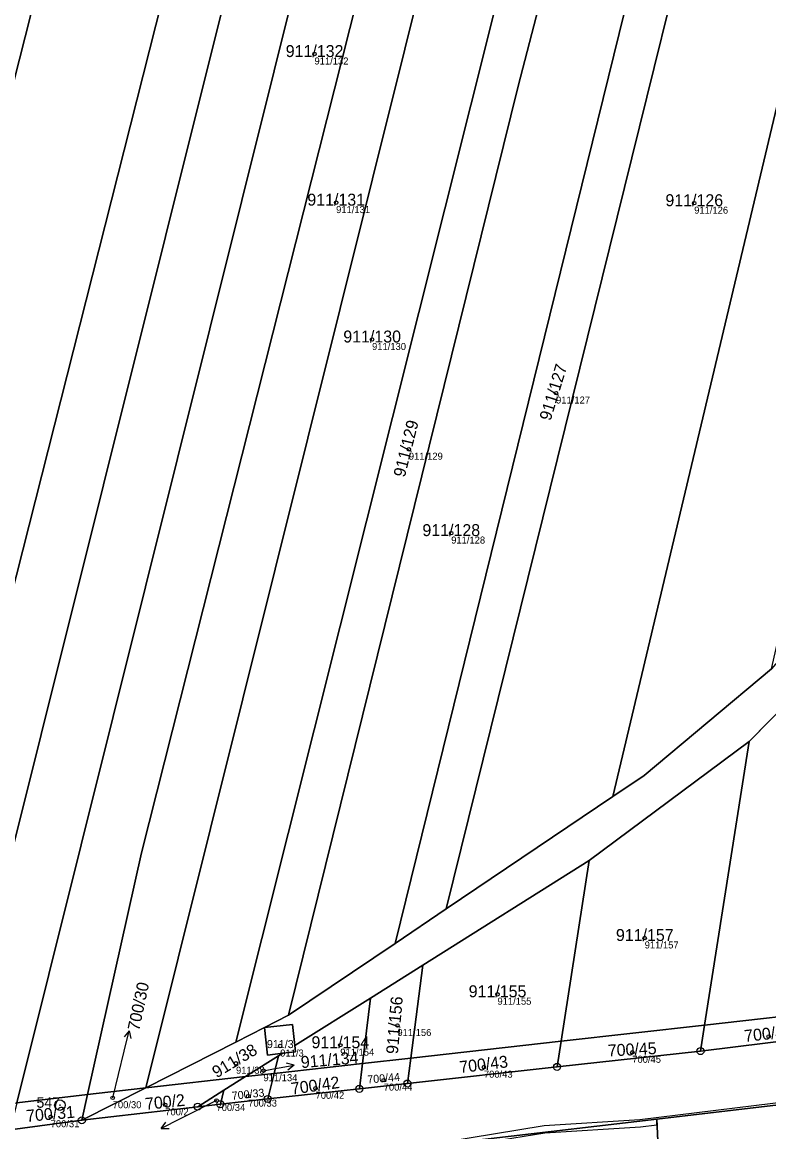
# Model space of a CAD drawing. Extents: x -603967 to -594699, y -1179315 to -1165625.
# Drawn here: x -596821.9 to -596715.6, y -1172077.4 to -1171919.4 of the extents above; entities that cross this region are included whole.
import ezdxf

# ---------------------------------------------------------------- set-up
doc = ezdxf.new("R2010")
doc.units = 0
for name, color, linetype in [('Definiční body', 7, 'Continuous'), ('Hranice parcel', 7, 'Continuous'), ('Parcelní čísla', 7, 'Continuous'), ('Polygon parcely', 7, 'Continuous'), ('Pop  PČ popisy', 7, 'Continuous'), ('Věcná břemena k části', 7, 'Continuous'), ('Značky bodu BP', 7, 'Continuous')]:
    doc.layers.add(name, color=color, linetype=linetype)

msp = doc.modelspace()

# ---------------------------------------------------------------- linework, layer by layer
at = {"layer": 'Definiční body'}
for centre in [(-596780.26, -1171923.92994), (-596777.18, -1171945.08994), (-596726.18, -1171945.16994), (-596772.06, -1171964.57994), (-596745.85, -1171972.20994), (-596766.82, -1171980.20994), (-596760.79, -1171992.14994), (-596733.23, -1172049.80994), (-596754.2, -1172057.81994), (-596768.45, -1172062.26994), (-596715.56, -1172063.82994), (-596785.14, -1172065.19994), (-596776.59, -1172065.07994), (-596735, -1172066.08994), (-596791.44, -1172067.64994), (-596787.53, -1172068.70994), (-596756.13, -1172068.20994), (-596770.4, -1172070.04994), (-596780.11, -1172071.21994), (-596809, -1172072.55994), (-596794.22, -1172072.94994), (-596789.7, -1172072.32994), (-596801.52, -1172073.56994), (-596817.84, -1172075.26994)]:
    msp.add_circle(centre, 0.25, dxfattribs=at)
at = {"layer": 'Hranice parcel'}
for p, q in [((-596718.34, -1172021.81), (-596692.4, -1171995.43)), ((-596741.13, -1172038.79), (-596718.34, -1172021.81)), ((-596724.7, -1172062.23), (-596718.34, -1172021.81)), ((-596737.77, -1172029.67), (-596761.52, -1172045.67)), ((-596764.85, -1172053.69), (-596741.13, -1172038.79)), ((-596745.13, -1172064.52), (-596741.13, -1172038.79)), ((-596761.52, -1172045.67), (-596768.78, -1172050.57)), ((-596768.78, -1172050.57), (-596783.97, -1172060.8)), ((-596772.3, -1172058.37), (-596764.85, -1172053.69)), ((-596764.85, -1172053.69), (-596766.56, -1172066.92)), ((-596783.08, -1172065.14), (-596772.3, -1172058.37)), ((-596773.43, -1172067.69), (-596772.3, -1172058.37)), ((-596705.38, -1172060.06), (-596724.7, -1172062.23)), ((-596783.97, -1172060.8), (-596787.39, -1172062.57)), ((-596787.39, -1172062.57), (-596783.41, -1172062.12)), ((-596783.41, -1172062.12), (-596783.08, -1172065.14)), ((-596787.39, -1172062.57), (-596791.46, -1172064.64)), ((-596786.95, -1172066.47), (-596787.39, -1172062.57)), ((-596724.7, -1172062.23), (-596745.13, -1172064.52)), ((-596725.28, -1172065.92), (-596724.7, -1172062.23)), ((-596725.28, -1172065.92), (-596706.08, -1172063.55)), ((-596791.46, -1172064.64), (-596804.29, -1172071.14)), ((-596745.13, -1172064.52), (-596766.56, -1172066.92)), ((-596745.71, -1172068.16), (-596745.13, -1172064.52)), ((-596790.08, -1172069.55), (-596785.41, -1172066.61)), ((-596784.79, -1172066.22), (-596786.95, -1172066.47)), ((-596786.02, -1172069.1), (-596785.41, -1172066.61)), ((-596785.41, -1172066.61), (-596784.79, -1172066.22)), ((-596766.56, -1172066.92), (-596773.43, -1172067.69)), ((-596766.56, -1172066.92), (-596767.02, -1172070.53)), ((-596745.71, -1172068.16), (-596725.28, -1172065.92)), ((-596773.43, -1172067.69), (-596786.02, -1172069.1)), ((-596773.87, -1172071.29), (-596773.43, -1172067.69)), ((-596767.02, -1172070.53), (-596745.71, -1172068.16)), ((-596790.08, -1172069.55), (-596804.29, -1172071.14)), ((-596793.18, -1172071.5), (-596790.08, -1172069.55)), ((-596786.02, -1172069.1), (-596790.08, -1172069.55)), ((-596786.92, -1172072.73), (-596786.02, -1172069.1)), ((-596804.29, -1172071.14), (-596813.4, -1172075.77)), ((-596796.88, -1172073.83), (-596793.18, -1172071.5)), ((-596793.18, -1172071.5), (-596793.67, -1172073.48)), ((-596786.92, -1172072.73), (-596773.87, -1172071.29)), ((-596773.87, -1172071.29), (-596767.02, -1172070.53)), ((-596812.58, -1172072.1), (-596822.64, -1172073.28)), ((-596812.58, -1172072.1), (-596813.4, -1172075.77)), ((-596793.67, -1172073.48), (-596786.92, -1172072.73)), ((-596709.32, -1172073.01), (-596731.52, -1172075.61)), ((-596813.4, -1172075.77), (-596796.88, -1172073.83)), ((-596796.88, -1172073.83), (-596793.67, -1172073.48)), ((-596823.6, -1172077.13), (-596813.4, -1172075.77)), ((-596731.52, -1172075.61), (-596755.09, -1172078.34)), ((-596731.52, -1172075.61), (-596729.67, -1172116))]:
    msp.add_line(p, q, dxfattribs=at)
for points in [[(-596860.64, -1172079.9), (-596855.65, -1172056.04), (-596784.82, -1171776.95), (-596751.75, -1171640.6)], [(-596842.58, -1172076.46), (-596782.13, -1171837.9), (-596745.57, -1171692.32), (-596733.85, -1171640.88)], [(-596725.01, -1171641.01), (-596749.75, -1171743.78), (-596774.96, -1171843.56), (-596828.06, -1172056.21), (-596832.9, -1172074.65)], [(-596715.61, -1171641.15), (-596731.07, -1171706.01), (-596822.64, -1172073.28)], [(-596706.66, -1171641.29), (-596723.53, -1171715.68), (-596804.88, -1172037.67), (-596812.58, -1172072.1)], [(-596698.11, -1171641.43), (-596716.69, -1171719.87), (-596804.29, -1172071.14)], [(-596688.26, -1171641.58), (-596691.61, -1171658.85), (-596709.62, -1171738.29), (-596791.46, -1172064.64)], [(-596680.83, -1171641.69), (-596726.19, -1171831.91), (-596751.27, -1171928.52), (-596783.97, -1172060.8)], [(-596671.46, -1171641.83), (-596677.57, -1171672.4), (-596701.96, -1171779.19), (-596768.78, -1172050.57)], [(-596666.17, -1171641.91), (-596670.71, -1171668.9), (-596684.25, -1171728.86), (-596700.1, -1171797.33), (-596761.52, -1172045.67)], [(-596651.64, -1171642.14), (-596655.01, -1171667.88), (-596688.58, -1171822.7), (-596737.77, -1172029.67)], [(-596715.18, -1172011.49), (-596733.29, -1172026.65), (-596737.77, -1172029.67)], [(-596783.08, -1172065.14), (-596782.98, -1172066.02), (-596784.79, -1172066.22)], [(-596804.29, -1172071.14), (-596806.36, -1172071.37), (-596812.58, -1172072.1)]]:
    msp.add_lwpolyline(points, dxfattribs=at)
at = {"layer": 'Polygon parcely'}
for points in [[(-596784.82, -1171776.95), (-596751.75, -1171640.6), (-596757.97, -1171640.5), (-596768.62, -1171640.34), (-596798.16, -1171764.25), (-596861.99, -1172011.73), (-596875.03, -1172065.74), (-596878.39, -1172083.56), (-596860.64, -1172079.9), (-596855.65, -1172056.04)], [(-596782.13, -1171837.9), (-596745.57, -1171692.32), (-596733.85, -1171640.88), (-596743.82, -1171640.72), (-596751.75, -1171640.6), (-596784.82, -1171776.95), (-596855.65, -1172056.04), (-596860.64, -1172079.9), (-596856.7, -1172079.09), (-596842.58, -1172076.46)], [(-596842.58, -1172076.46), (-596832.9, -1172074.65), (-596828.06, -1172056.21), (-596774.96, -1171843.56), (-596749.75, -1171743.78), (-596725.01, -1171641.01), (-596732.91, -1171640.89), (-596733.85, -1171640.88), (-596745.57, -1171692.32), (-596782.13, -1171837.9)], [(-596828.06, -1172056.21), (-596832.9, -1172074.65), (-596830.41, -1172074.19), (-596822.64, -1172073.28), (-596731.07, -1171706.01), (-596715.61, -1171641.15), (-596720.4, -1171641.08), (-596725.01, -1171641.01), (-596749.75, -1171743.78), (-596774.96, -1171843.56)], [(-596822.64, -1172073.28), (-596812.58, -1172072.1), (-596804.88, -1172037.67), (-596723.53, -1171715.68), (-596706.66, -1171641.29), (-596715.61, -1171641.15), (-596731.07, -1171706.01)], [(-596812.58, -1172072.1), (-596806.36, -1172071.37), (-596804.29, -1172071.14), (-596716.69, -1171719.87), (-596698.11, -1171641.43), (-596705.63, -1171641.31), (-596706.66, -1171641.29), (-596723.53, -1171715.68), (-596804.88, -1172037.67)], [(-596804.29, -1172071.14), (-596791.46, -1172064.64), (-596709.62, -1171738.29), (-596691.61, -1171658.85), (-596688.26, -1171641.58), (-596693.33, -1171641.5), (-596698.11, -1171641.43), (-596716.69, -1171719.87)], [(-596709.62, -1171738.29), (-596791.46, -1172064.64), (-596787.39, -1172062.57), (-596783.97, -1172060.8), (-596751.27, -1171928.52), (-596726.19, -1171831.91), (-596680.83, -1171641.69), (-596688.26, -1171641.58), (-596691.61, -1171658.85)], [(-596783.97, -1172060.8), (-596768.78, -1172050.57), (-596701.96, -1171779.19), (-596677.57, -1171672.4), (-596671.46, -1171641.83), (-596680.83, -1171641.69), (-596726.19, -1171831.91), (-596751.27, -1171928.52)], [(-596768.78, -1172050.57), (-596761.52, -1172045.67), (-596700.1, -1171797.33), (-596684.25, -1171728.86), (-596670.71, -1171668.9), (-596666.17, -1171641.91), (-596667.7, -1171641.89), (-596671.46, -1171641.83), (-596677.57, -1171672.4), (-596701.96, -1171779.19)], [(-596670.71, -1171668.9), (-596684.25, -1171728.86), (-596700.1, -1171797.33), (-596761.52, -1172045.67), (-596737.77, -1172029.67), (-596688.58, -1171822.7), (-596655.01, -1171667.88), (-596651.64, -1171642.14), (-596655.52, -1171642.08), (-596666.17, -1171641.91)], [(-596655.01, -1171667.88), (-596688.58, -1171822.7), (-596737.77, -1172029.67), (-596733.29, -1172026.65), (-596715.18, -1172011.49), (-596666.38, -1171798.6), (-596652.52, -1171725.52), (-596641, -1171673.92), (-596638.2, -1171642.35), (-596642.55, -1171642.28), (-596651.64, -1171642.14)], [(-596705.38, -1172060.06), (-596692.4, -1171995.43), (-596718.34, -1172021.81), (-596724.7, -1172062.23)], [(-596724.7, -1172062.23), (-596718.34, -1172021.81), (-596741.13, -1172038.79), (-596745.13, -1172064.52)], [(-596766.56, -1172066.92), (-596745.13, -1172064.52), (-596741.13, -1172038.79), (-596764.85, -1172053.69)], [(-596773.43, -1172067.69), (-596766.56, -1172066.92), (-596764.85, -1172053.69), (-596772.3, -1172058.37)], [(-596782.98, -1172066.02), (-596784.79, -1172066.22), (-596785.41, -1172066.61), (-596786.02, -1172069.1), (-596773.43, -1172067.69), (-596772.3, -1172058.37), (-596783.08, -1172065.14)], [(-596725.28, -1172065.92), (-596706.08, -1172063.55), (-596705.38, -1172060.06), (-596724.7, -1172062.23)], [(-596786.95, -1172066.47), (-596784.79, -1172066.22), (-596782.98, -1172066.02), (-596783.08, -1172065.14), (-596783.41, -1172062.12), (-596787.39, -1172062.57)], [(-596787.39, -1172062.57), (-596791.46, -1172064.64), (-596804.29, -1172071.14), (-596790.08, -1172069.55), (-596785.41, -1172066.61), (-596784.79, -1172066.22), (-596786.95, -1172066.47)], [(-596725.28, -1172065.92), (-596724.7, -1172062.23), (-596745.13, -1172064.52), (-596745.71, -1172068.16)], [(-596767.02, -1172070.53), (-596745.71, -1172068.16), (-596745.13, -1172064.52), (-596766.56, -1172066.92)], [(-596786.02, -1172069.1), (-596785.41, -1172066.61), (-596790.08, -1172069.55)], [(-596773.87, -1172071.29), (-596767.02, -1172070.53), (-596766.56, -1172066.92), (-596773.43, -1172067.69)], [(-596786.92, -1172072.73), (-596773.87, -1172071.29), (-596773.43, -1172067.69), (-596786.02, -1172069.1)], [(-596813.4, -1172075.77), (-596796.88, -1172073.83), (-596793.18, -1172071.5), (-596790.08, -1172069.55), (-596804.29, -1172071.14)], [(-596786.92, -1172072.73), (-596786.02, -1172069.1), (-596790.08, -1172069.55), (-596793.18, -1172071.5), (-596793.67, -1172073.48)], [(-596813.4, -1172075.77), (-596804.29, -1172071.14), (-596806.36, -1172071.37), (-596812.58, -1172072.1)], [(-596793.67, -1172073.48), (-596793.18, -1172071.5), (-596796.88, -1172073.83)], [(-596813.4, -1172075.77), (-596812.58, -1172072.1), (-596822.64, -1172073.28), (-596823.6, -1172077.13)], [(-596729.67, -1172116), (-596707.12, -1172113.29), (-596709.32, -1172073.01), (-596731.52, -1172075.61)], [(-596755.09, -1172078.34), (-596754.53, -1172125.79), (-596739.79, -1172124.76), (-596740.18, -1172117.22), (-596729.67, -1172116), (-596731.52, -1172075.61)]]:
    msp.add_lwpolyline(points, close=True, dxfattribs=at)
for points in [[(-596783.08, -1172065.14), (-596772.3, -1172058.37), (-596764.85, -1172053.69), (-596741.13, -1172038.79), (-596718.34, -1172021.81), (-596692.4, -1171995.43), (-596668.6, -1171971.23), (-596660.59, -1171963.08), (-596653.35, -1171955.72), (-596646.21, -1171948.46), (-596637.9, -1171939.47), (-596630.53, -1171929.86), (-596623.06, -1171920.13), (-596616.01, -1171912.53), (-596609.77, -1171907.25), (-596600.89, -1171899.73), (-596594.45, -1171894.83), (-596587.53, -1171889.33), (-596580.8, -1171885.78), (-596574.08, -1171882.1), (-596567.57, -1171878.54), (-596560.55, -1171874.7), (-596553.65, -1171870.92)], [(-596627.33, -1171917.09), (-596634.75, -1171928.19), (-596644.04, -1171942.08), (-596651.33, -1171948.59), (-596659.47, -1171955.86), (-596667, -1171962.59), (-596688.82, -1171982.07), (-596693.83, -1171986.54), (-596715.18, -1172011.49), (-596733.29, -1172026.65), (-596737.77, -1172029.67), (-596761.52, -1172045.67), (-596768.78, -1172050.57), (-596783.97, -1172060.8), (-596787.39, -1172062.57), (-596783.41, -1172062.12), (-596783.08, -1172065.14)], [(-596828.27, -1172087.31), (-596807.73, -1172085.05), (-596806.18, -1172084.88), (-596799.11, -1172083.92), (-596791.19, -1172082.85), (-596782.35, -1172081.65), (-596772.8, -1172080.36), (-596766.81, -1172079.55), (-596763.76, -1172079.34), (-596755.09, -1172078.34), (-596731.52, -1172075.61), (-596709.32, -1172073.01), (-596697.04, -1172071.57), (-596700.13, -1172068.83), (-596705.84, -1172063.76), (-596706.08, -1172063.55), (-596725.28, -1172065.92), (-596745.71, -1172068.16), (-596767.02, -1172070.53), (-596773.87, -1172071.29), (-596786.92, -1172072.73), (-596793.67, -1172073.48), (-596796.88, -1172073.83)], [(-596796.88, -1172073.83), (-596813.4, -1172075.77), (-596823.6, -1172077.13)]]:
    msp.add_lwpolyline(points, dxfattribs=at)
at = {"layer": 'Pop  PČ popisy'}
for p, q in [((-596806.644, -1172063.018), (-596807.372, -1172063.869)), ((-596807.37, -1172065.93), (-596806.644, -1172063.018)), ((-596806.644, -1172063.018), (-596806.4, -1172064.111)), ((-596809, -1172072.56), (-596807.37, -1172065.93)), ((-596787.53, -1172068.71), (-596786.12, -1172068.46)), ((-596786.12, -1172068.46), (-596783.165, -1172067.939)), ((-596783.165, -1172067.939), (-596784.238, -1172067.62)), ((-596783.165, -1172067.939), (-596784.064, -1172068.606)), ((-596794.22, -1172072.95), (-596799.41, -1172075.56)), ((-596799.41, -1172075.56), (-596802.084, -1172076.922)), ((-596802.084, -1172076.922), (-596801.419, -1172076.022)), ((-596802.084, -1172076.922), (-596800.964, -1172076.914))]:
    msp.add_line(p, q, dxfattribs=at)
at = {"layer": 'Věcná břemena k části'}
for points in [[(-596635.39, -1172064.89), (-596621.15, -1172063.34), (-596606.98, -1172061.8), (-596593.21, -1172060.3), (-596584.6, -1172059.36), (-596579.44, -1172058.8), (-596576.81, -1172058.27), (-596655.6, -1172066.99), (-596696.02, -1172071.05), (-596733.9, -1172075.72), (-596747.53, -1172076.54), (-596765.15, -1172079.44), (-596763.76, -1172079.34), (-596755.09, -1172078.34), (-596731.52, -1172075.61), (-596709.32, -1172073.01), (-596697.04, -1172071.57), (-596688.89, -1172070.7), (-596676.08, -1172069.31), (-596668.46, -1172068.48), (-596646.74, -1172066.12)], [(-596763.76, -1172079.34), (-596763.77, -1172080.22), (-596755.08, -1172078.79), (-596747.43, -1172077.54), (-596733.81, -1172076.71), (-596731.48, -1172076.42), (-596731.52, -1172075.61), (-596755.09, -1172078.34)]]:
    msp.add_lwpolyline(points, close=True, dxfattribs=at)
at = {"layer": 'Značky bodu BP'}
for centre, radius in [((-596725.28, -1172065.91988), 0.5), ((-596725.28, -1172065.91988), 0.0303), ((-596745.71, -1172068.15988), 0.5), ((-596745.71, -1172068.15988), 0.0303), ((-596767.02, -1172070.52988), 0.5), ((-596773.87, -1172071.28988), 0.5), ((-596773.87, -1172071.28988), 0.0303), ((-596767.02, -1172070.52988), 0.0303), ((-596816.52, -1172073.60982), 0.75), ((-596793.67, -1172073.47988), 0.5), ((-596786.92, -1172072.72988), 0.5), ((-596786.92, -1172072.72988), 0.0303), ((-596816.52, -1172073.60982), 0.03), ((-596796.88, -1172073.82988), 0.5), ((-596796.88, -1172073.82988), 0.0303), ((-596793.67, -1172073.47988), 0.0303), ((-596813.4, -1172075.76988), 0.5), ((-596813.4, -1172075.76988), 0.0303)]:
    msp.add_circle(centre, radius, dxfattribs=at)

# ---------------------------------------------------------------- texts
at = {"layer": 'Definiční body'}
for s, p in [('911/132', (-596780.26, -1171925.419)), ('911/131', (-596777.18, -1171946.579)), ('911/126', (-596726.18, -1171946.659)), ('911/130', (-596772.06, -1171966.069)), ('911/127', (-596745.85, -1171973.699)), ('911/129', (-596766.82, -1171981.699)), ('911/128', (-596760.79, -1171993.639)), ('911/157', (-596733.23, -1172051.299)), ('911/155', (-596754.2, -1172059.309)), ('911/156', (-596768.45, -1172063.759)), ('911/3', (-596785.14, -1172066.689)), ('911/154', (-596776.59, -1172066.569)), ('700/45', (-596735, -1172067.579)), ('911/38', (-596791.44, -1172069.139)), ('911/134', (-596787.53, -1172070.199)), ('700/43', (-596756.13, -1172069.699)), ('700/42', (-596780.11, -1172072.709)), ('700/44', (-596770.4, -1172071.539)), ('700/30', (-596809, -1172074.049)), ('700/33', (-596789.7, -1172073.819)), ('700/2', (-596801.52, -1172075.059)), ('700/34', (-596794.22, -1172074.439)), ('700/31', (-596817.84, -1172076.759))]:
    msp.add_text(s, height=0.999996, dxfattribs=at).set_placement(p)
at = {"layer": 'Parcelní čísla'}
for s, height, p in [('911/132', 1.699998, (-596784.356, -1171924.355)), ('911/131', 1.699998, (-596781.276, -1171945.515)), ('911/126', 1.699998, (-596730.276, -1171945.595)), ('911/130', 1.699998, (-596776.156, -1171965.005)), ('911/128', 1.699998, (-596764.886, -1171992.575)), ('911/157', 1.699998, (-596737.326, -1172050.235)), ('911/155', 1.699998, (-596758.296, -1172058.245)), ('911/154', 1.699998, (-596780.686, -1172065.505)), ('911/3', 1.14, (-596787.041, -1172065.485))]:
    msp.add_text(s, height=height, dxfattribs=at).set_placement(p)
for s, height, rotation, p in [('911/127', 1.699998, 73, (-596746.641, -1171976.251)), ('911/129', 1.699998, 76, (-596767.398, -1171984.287)), ('700/30', 1.699998, 78, (-596805.244, -1172063.108)), ('911/156', 1.699998, 85, (-596768.383, -1172066.388)), ('700/46', 1.699998, 6, (-596718.962, -1172064.615)), ('911/38', 1.699998, 31, (-596794.192, -1172069.799)), ('700/45', 1.699998, 3, (-596738.439, -1172066.695)), ('911/134', 1.699998, 5, (-596782.132, -1172068.353)), ('700/43', 1.699998, 7, (-596759.518, -1172069.054)), ('700/42', 1.699998, 8, (-596783.483, -1172072.123)), ('700/44', 1.14, 5, (-596772.69, -1172070.536)), ('700/33', 1.14, 6, (-596791.982, -1172072.856)), ('700/2', 1.699998, 6, (-596804.296, -1172074.289)), ('700/31', 1.699998, 5, (-596821.256, -1172075.995))]:
    msp.add_text(s, height=height, rotation=rotation, dxfattribs=at).set_placement(p)
at = {"layer": 'Značky bodu BP'}
msp.add_text('547', height=1.5, dxfattribs=at).set_placement((-596819.856, -1172073.985))

doc.saveas('drawing.dxf')
